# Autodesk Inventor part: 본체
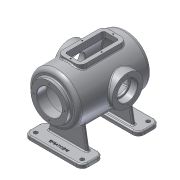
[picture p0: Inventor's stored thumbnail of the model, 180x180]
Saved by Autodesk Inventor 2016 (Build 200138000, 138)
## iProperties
Created: 2016-02
Part Number: 본체
Material: 알루미늄 6061
Document SubType Name: Modeling
Designer: mduedu
Density: 2.71 g/cm^3
Mass: 3305.63 g
Surface Area: 2487.05 cm^2
Volume: 1219.79 cm^3
Appearance: 알루미늄 - 평지
Author: mduedu
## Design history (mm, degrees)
sketch "스케치2"
  geometry: L1 (0, 100)-(0, -100); L2 (65, -87.083)-(65, 100); L3 (65, 100)-(0, 100); A1 r 170 centre (0, 70) between (0, -100) and (65, -87.083); 2 further points
  constraints: 6 end point, 2 point on circle, 1 centre point, 1 coincident, 1 horizontal, 1 midpoint, 1 parallel, 1 point on line, 1 vertical
  dimensions: "d3" = 200 distance of L1.start L1.end; "d5" = 130 diameter of L2 L1; "d6" = 170 radius of A1
revolve "회전1" sketch "스케치2" stored, may be unused: angle "d7" = 90 deg
sketch "스케치3"
  geometry: C1 r 47.5 at (0, 0); 1 further point
  constraints: 1 centre point, 1 coincident
  dimensions: "d8" = 95 diameter of C1
extrude "돌출2" join sketch "스케치3" distance "d10" = 10; taper "d11" = 0 deg
sketch "스케치5"
  geometry: L1 (47.5, 110)-(47.5, 100) reference; L2 (47.5, 100)-(65, 100) reference; L3 (65, 100)-(65, -87.083) reference; L4 (-65, -87.083)-(-65, 100) reference; L5 (-65, 100)-(-47.5, 100) reference; L6 (-47.5, 100)-(-47.5, 110) reference; L7 (-47.5, 110)-(47.5, 110) reference; L8 (55, 85)-(55, -80.25); L9 (0, 85)-(55, 85); L10 (0, 85)-(0, -90); A1 r 170 centre (0, 70) between (-65, -87.083) and (0, -100) reference; A2 r 170 centre (0, 70) between (0, -100) and (65, -87.083) reference; A3 r 160 centre (0, 70) between (0, -90) and (55, -80.25); 1 further point
  constraints: 6 end point, 2 point on circle, 1 centre point, 1 parallel, 1 perpendicular, 1 point on line, 1 vertical
  dimensions: "d13" = 10 distance between parallel lines of L3 L8; "d14" = 10 radial gap between concentric circles of A3 A1; "d15" = 15 distance between parallel lines of L9 L2
revolve "회전2" sketch "스케치5" stored, may be unused: angle "d16" = 90 deg
hole "구멍1" diameter "d19" = 65; stored, may be unused: countersink angle "d23" = 90 deg, drill point angle "d25" = 118 deg; dims "d17" = 10, "d18" = 10, "d20" = 6, "d21" = 4, "d22" = 2, "d24" = 8
node "작업 평면1"
sketch "스케치6"
  geometry: L1 (47.5, 110)-(-47.5, 110) reference; C1 r 40 at (0, -17); 1 further point
  constraints: 1 centre point, 1 vertical alignment
  dimensions: "d27" = 80 diameter of C1; "d29" = 127 distance from line of C1.centre L1
extrude "돌출3" join sketch "스케치6" stored distance "d30" = 10; taper "d31" = 0 deg
hole "구멍2" diameter "d34" = 42; stored, may be unused: countersink angle "d38" = 90 deg, drill point angle "d40" = 118 deg; dims "d32" = 10, "d33" = 10, "d35" = 6, "d36" = 52, "d37" = 18, "d39" = 8
sketch "스케치7" dims "d41" = 65
  geometry: C1 r 40 at (0, 0) reference; 3 further points
  constraints: 2 vertical alignment, 1 coincident, 2 other
hole "구멍3" sketch "스케치7" at (0, 32.5) diameter "d43" = 3.242; stored, may be unused: countersink angle "d47" = 90 deg, drill point angle "d49" = 118 deg; dims "d44" = 11, "d45" = 13, "d46" = 18, "d48" = 13
sketch "스케치8" dims "d53" = 80
  geometry: 3 further points
  constraints: 2 vertical alignment, 1 coincident, 2 other
hole "구멍4" sketch "스케치8" at (0, 40) diameter "d56" = 3.242; stored, may be unused: countersink angle "d60" = 90 deg, drill point angle "d62" = 118 deg; dims "d57" = 11, "d58" = 13, "d59" = 18, "d61" = 13
fillet "모깎기1" dims "d66" = 10
fillet "모깎기2" dims "d67" = 3
fillet "모깎기3" dims "d68" = 0.3
chamfer "모따기1" distance "d69" = 1; stored, may be unused: second distance "d70" = 2, angle "d71" = 45 deg
node "작업 평면2"
sketch "스케치9"
  geometry: L1 (75, 100)-(-75, 100); L2 (-75, 100)-(-75, -100); L3 (-75, -100)-(75, -100); L4 (75, -100)-(75, 100); 1 further point
  constraints: 8 end point, 2 parallel, 1 horizontal, 1 perpendicular
  dimensions: "d73" = 200 distance of L3.end L1.start; "d75" = 150 distance of L2.end L3.end; "d76" = 100 distance from line of L1 point (0, 0); "d77" = 75 distance from line of L4 point (0, 0)
extrude "돌출4" join sketch "스케치9" distance "d78" = 10; taper "d79" = 0 deg
sketch "스케치10"
  geometry: L1 (-75, -100)-(75, -100) reference; L2 (75, 100)-(-75, 100) reference; L3 (0, -100)-(0, 100); L4 (-75, 100)-(-75, -100) reference; L5 (75, -100)-(75, 100) reference; L6 (-75, 0)-(75, 0); L7 (-50, -63)-(50, -63); L8 (50, -63)-(50, -55); L9 (50, -55)-(-50, -55); L10 (-50, -55)-(-50, -63); L11 (-50, 63)-(50, 63); L12 (50, 63)-(50, 55); L13 (50, 55)-(-50, 55); L14 (-50, 55)-(-50, 63); 1 further point
  constraints: 20 end point, 4 midpoint, 4 symmetric about line, 2 parallel, 1 horizontal, 1 perpendicular, 1 other
  dimensions: "d80" = 8 distance of L9.end L7.start; "d82" = 100 distance of L7.start L7.end; "d83" = 55 distance between parallel lines of L9 L6
extrude "돌출5" join sketch "스케치10" stored distance "d84" = 10; taper "d85" = 0 deg
feature "면 기울기1" dims angle "d86" = 10 deg
sketch "스케치11"
  geometry: L1 (-110, 55)-(-51.482, 55) reference; L2 (-110, -55)-(-51.482, -55) reference; L3 (-95, 55)-(-95, -55); L4 (-65, 90)-(-65, -80.25) reference; 1 further point
  constraints: 2 end point, 2 point on line, 1 perpendicular
  dimensions: "d87" = 30 distance between parallel lines of L3 L4
feature "리브1" sketch "스케치11" dims "d88" = 1, "d89" = 8, "d90" = 0, "d91" = 0, "d92" = 1, "d93" = 1
sketch "스케치12"
  geometry: L1 (-110, 55)-(-51.482, 55) reference; L2 (-110, -55)-(-51.482, -55) reference; L3 (-110, 100)-(-110, -100) reference; L4 (-120, 152)-(-120, -142) reference; L5 (-110, 45)-(-120, 45); L6 (-120, 45)-(-120, -45); L7 (-120, -45)-(-110, -45); L8 (-110, -45)-(-110, 45); 1 further point
  constraints: 8 end point, 2 parallel, 2 point on line, 1 horizontal, 1 perpendicular
  dimensions: "d94" = 10 distance between parallel lines of L7 L2; "d95" = 10 distance between parallel lines of L1 L5
extrude "돌출6" cut sketch "스케치12" stored distance "d96" = 10; taper "d97" = 0 deg
fillet "모깎기4" dims "d98" = 15
sketch "스케치13"
  geometry: C1 r 5 at (-60, -85); C2 r 5 at (60, -85); C3 r 5 at (60, 85); C4 r 5 at (-60, 85); A1 r 15 centre (-60, -85) between (-75, -85) and (-60, -100) reference; A2 r 15 centre (60, -85) between (60, -100) and (75, -85) reference; A3 r 15 centre (60, 85) between (75, 85) and (60, 100) reference; A4 r 15 centre (-60, 85) between (-60, 100) and (-75, 85) reference; 1 further point
  constraints: 4 centre point, 4 coincident, 3 equal radius
  dimensions: "d99" = 10 diameter of C1
extrude "돌출7" cut sketch "스케치13" stored distance "d101" = 10; taper "d102" = 0 deg
fillet "모깎기5" dims "d103" = 3, "d104" = 3
fillet "모깎기6" dims "d105" = 3
sketch "스케치14"
  geometry: L1 (-60, -100)-(60, -100) reference; 2 further points
  constraints: 1 vertical alignment, 1 other
  dimensions: "d106" = 15 distance from line of point (0, -85) L1
feature "엠보싱1" sketch "스케치14" dims "d3" = 200, "d5" = 130, "d6" = 170, "d14" = 10, "d107" = 0.5, "d108" = 0
node "작업 평면3"
sketch "스케치15"
  geometry: L1 (-30, 60)-(30, 60); L2 (30, 60)-(30, -60); L3 (30, -60)-(-30, -60); L4 (-30, -60)-(-30, 60); 2 further points
  constraints: 8 end point, 2 parallel, 1 horizontal, 1 midpoint, 1 perpendicular, 1 vertical alignment
  dimensions: "d110" = 60 distance of L2.end L3.end; "d112" = 60 distance from line of L3 point (0, 0); "d113" = 120 distance of L1.end L2.end
extrude "돌출8" join sketch "스케치15" stored distance "d114" = 10; taper "d115" = 0 deg
fillet "모깎기7" dims "d116" = 15
sketch "스케치16"
  geometry: L1 (-30, -45)-(-30, 45) reference; L2 (-15, 60)-(15, 60) reference; L3 (30, 45)-(30, -45) reference; L4 (15, -60)-(-15, -60) reference; L5 (15, 50)-(-15, 50); L6 (-20, 45)-(-20, -45); L7 (-15, -50)-(15, -50); L8 (20, -45)-(20, 45); A1 r 15 centre (-15, -45) between (-30, -45) and (-15, -60) reference; A2 r 15 centre (-15, 45) between (-15, 60) and (-30, 45) reference; A3 r 15 centre (15, 45) between (30, 45) and (15, 60) reference; A4 r 15 centre (15, -45) between (15, -60) and (30, -45) reference; A5 r 5 centre (-15, 45) between (-15, 50) and (-20, 45); A6 r 5 centre (-15, -45) between (-20, -45) and (-15, -50); A7 r 5 centre (15, -45) between (15, -50) and (20, -45); A8 r 5 centre (15, 45) between (20, 45) and (15, 50); 1 further point
  constraints: 8 end point, 8 point on circle, 4 centre point, 7 other
  dimensions: "d117" = 10 distance between parallel lines of L6 L1
extrude "돌출9" cut sketch "스케치16" stored distance "d118" = 10; taper "d119" = 0 deg
fillet "모깎기8" dims "d120" = 3
sketch "스케치17"
  geometry: L1 (-30, -45)-(-30, 45) reference; L2 (-15, 60)-(15, 60) reference; L3 (30, 45)-(30, -45) reference; L4 (15, -60)-(-15, -60) reference; L5 (20, -45)-(20, 45) reference; L6 (15, 50)-(-15, 50) reference; L7 (-20, 45)-(-20, -45) reference; L8 (-15, -50)-(15, -50) reference; L9 (15, 55)-(-15, 55); L10 (-25, 45)-(-25, -45); L11 (-15, -55)-(15, -55); L12 (25, -45)-(25, 45); A1 r 15 centre (-15, 45) between (-15, 60) and (-30, 45) reference; A2 r 15 centre (15, 45) between (30, 45) and (15, 60) reference; A3 r 15 centre (15, -45) between (15, -60) and (30, -45) reference; A4 r 15 centre (-15, -45) between (-30, -45) and (-15, -60) reference; A5 r 5 centre (15, -45) between (15, -50) and (20, -45) reference; A6 r 5 centre (15, 45) between (20, 45) and (15, 50) reference; A7 r 5 centre (-15, 45) between (-15, 50) and (-20, 45) reference; A8 r 5 centre (-15, -45) between (-20, -45) and (-15, -50) reference; A9 r 10 centre (-15, 45) between (-15, 55) and (-25, 45); A10 r 10 centre (-15, -45) between (-25, -45) and (-15, -55); A11 r 10 centre (15, -45) between (15, -55) and (25, -45); A12 r 10 centre (15, 45) between (25, 45) and (15, 55); 5 further points
  constraints: 8 end point, 8 point on circle, 4 centre point, 4 midpoint, 7 other
  dimensions: "d121" = 5 distance between parallel lines of L10 L1
hole "구멍5" sketch "스케치17" at (0, 55), (25, 0), (0, -55), (-25, 0) diameter "d122" = 3.242; stored, may be unused: countersink angle "d126" = 90 deg, drill point angle "d128" = 118 deg; dims "d123" = 9, "d124" = 13, "d125" = 18, "d127" = 11
fillet "모깎기9" dims "d129" = 3
node "솔리드2"
pattern_circular "원형 패턴1" dims angle "d51" = 360 deg
mirror "대칭1"
pattern_circular "원형 패턴2" dims angle "d64" = 360 deg
node "절단 모서리 투영1"
node "절단 모서리 투영2"
node "절단 모서리 투영3"
other parameters: "d26" = 75
